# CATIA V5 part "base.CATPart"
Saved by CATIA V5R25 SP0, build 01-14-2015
Part number: base
Bounding box of the stored display mesh (mm): x 0 to 100, y 0 to 15, z 0 to 10
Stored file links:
  C:\Users\Aidata\Downloads\chapter4\chapter4\base.CATPart
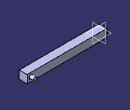
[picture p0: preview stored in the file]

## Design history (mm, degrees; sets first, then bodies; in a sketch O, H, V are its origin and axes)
Body1 (main body)
  Sketch1 on yz-plane, origin (0, 0, 0), H (0, 1, 0), V (0, 0, 1)
    line L1 (0, 0) -> (10, 0)
    line L2 (10, 0) -> (10, 10)
    line L3 (10, 10) -> (0, 10)
    line L4 (0, 10) -> (0, 0)
    length L2 = 10
    length L1 = 10
    horizontal: L1 H, L3 H
    vertical: L2 V, L4 V
  Pad1: profile Sketch1, direction (1, 0, 0), length 100
  Sketch2 on face of Pad1 from Sketch1.L2, origin (0, 10, 0), H (-1, 0, 0), V (0, 0, 1)
    circle A1 centre (-95, 5) radius 2.5
    point P1 (-95, 5)
    reference projected line E1 (0, 10) -> (-100, 10) from edge [face of Pad1 from Sketch1.L3 | face of Pad1 from Sketch1.L2]
    reference projected line E2 (-100, 0) -> (-100, 10) from edge [face of Pad1 from Sketch1.L2 | end face of Pad1]
    radius A1 = 2.5
    distance P1 E1 = 5
    distance P1 E2 = 5
  Pad2: profile Sketch2, direction (0, 1, 0), length 5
